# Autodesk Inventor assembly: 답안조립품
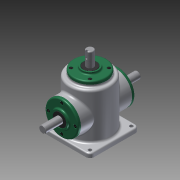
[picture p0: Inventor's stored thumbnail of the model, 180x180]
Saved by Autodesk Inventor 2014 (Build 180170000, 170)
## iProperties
Created: 2015-10
Part Number: 답안조립품
Document SubType Name: Assembly
Designer: SEC
Author: SEC
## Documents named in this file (14)
- C:\Users\SEC\Desktop\451007V1007\답안조립품.iam
- C:\Users\SEC\Desktop\451007V1007\1-본체.ipt
- C:\Users\SEC\Desktop\451007V1007\커버.ipt
- C:\Users\SEC\Desktop\451007V1007\베어링 6203.ipt
- C:\Users\SEC\Desktop\451007V1007\메인 축.ipt
- 메인 축.ipt
- C:\Users\SEC\Desktop\451007V1007\메인 베벨기어.ipt
- C:\Users\SEC\Desktop\451007V1007\서브 베벨기어.ipt
- C:\Users\SEC\Desktop\451007V1007\서브 축.ipt
- 서브 축.ipt
- C:\Users\SEC\Desktop\451007V1007\오일실.ipt
- C:\Users\SEC\Desktop\451007V1007\키 5x5.ipt
- C:\Users\SEC\Desktop\451007V1007\키 4x4.ipt
- C:\Users\SEC\Desktop\451007V1007\M4.ipt
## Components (13 placed, 2 different names)
1. 1-본체:1
2. M4:3
3. M4:4
4. M4:5
5. M4:6
6. M4:2
7. M4:7
8. M4:8
9. M4:9
10. M4:1
11. M4:10
12. M4:11
13. M4:12
